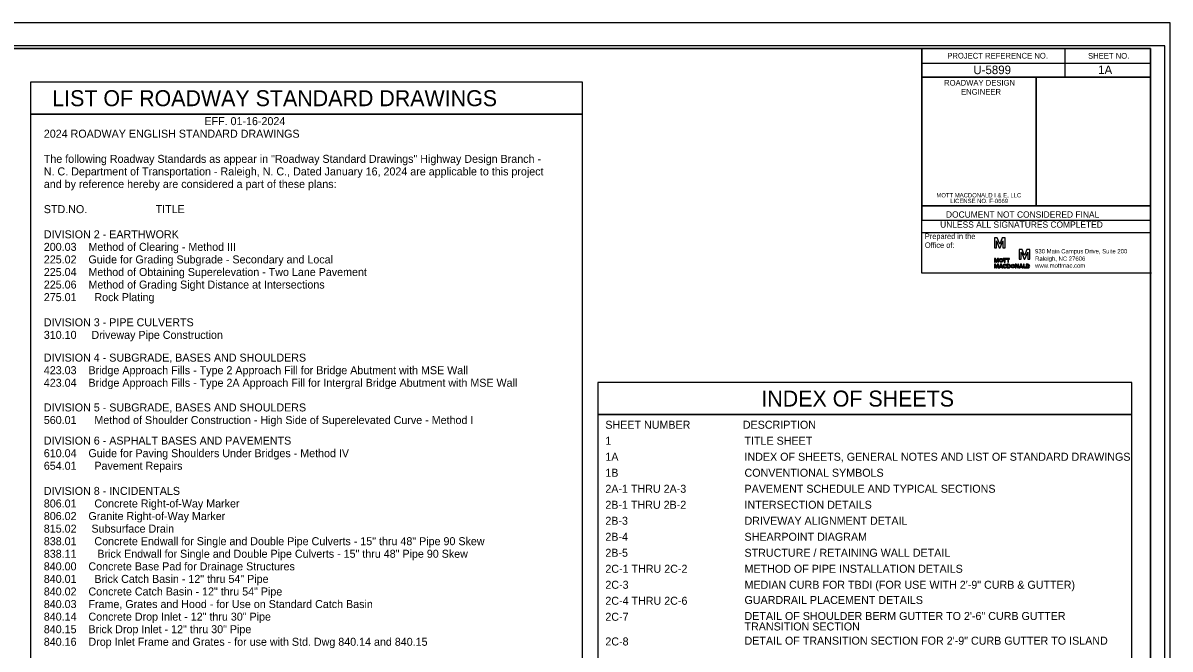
# Model space of a CAD drawing. Extents: x 93723152 to 93807327, y 70087853 to 70142603.
# Drawn here: x 93757166 to 93807327, y 70115212 to 70142603 of the extents above; entities that cross this region are included whole.
import ezdxf

# ---------------------------------------------------------------- set-up
doc = ezdxf.new("R2010")
doc.units = 0
for name, color, linetype in [('Default', 7, 'Continuous'), ('Old_Level_1', 7, 'Continuous'), ('Old_Level_2', 7, 'Continuous'), ('Old_Level_40', 7, 'Continuous'), ('Old_Level_42', 7, 'Continuous'), ('Old_Level_45', 7, 'Continuous'), ('Sheet Cutting Line CELL', 7, 'Continuous'), ('Sheet Data Field CELL', 7, 'Continuous'), ('Sheet Plan CELL', 7, 'Continuous'), ('Sheet Plot Border Inside CELL', 7, 'Continuous'), ('Sheet Plot Border Outside CELL', 7, 'Continuous'), ('Sheet Sticker Exception Certification CELL', 7, 'Continuous')]:
    doc.layers.add(name, color=color, linetype=linetype)

msp = doc.modelspace()

# ---------------------------------------------------------------- linework, layer by layer
at = {"layer": 'Old_Level_1'}
for points in [[(93757503, 70098101), (93781631, 70098101), (93781631, 70138611), (93757503, 70138611)], [(93782306, 70100674), (93805663, 70100674), (93805663, 70125470), (93782306, 70125470)]]:
    msp.add_lwpolyline(points, close=True, dxfattribs=at)
at = {"layer": 'Old_Level_2'}
for p, q in [((93799774, 70133195), (93799648, 70133195)), ((93799648, 70133195), (93799648, 70132768)), ((93799738, 70132768), (93799738, 70133075)), ((93799738, 70133075), (93799739, 70133075)), ((93799739, 70133075), (93799859, 70132768)), ((93799877, 70132931), (93799774, 70133195)), ((93799877, 70132927), (93799877, 70132931)), ((93799880, 70132927), (93799877, 70132927)), ((93799983, 70133195), (93799880, 70132931)), ((93799880, 70132931), (93799880, 70132927)), ((93799898, 70132768), (93800018, 70133076)), ((93800110, 70133195), (93799983, 70133195)), ((93800018, 70133076), (93800020, 70133076)), ((93800020, 70133076), (93800020, 70132768)), ((93800110, 70132768), (93800110, 70133195)), ((93799648, 70132768), (93799738, 70132768)), ((93799696, 70132301), (93799648, 70132301)), ((93799648, 70132301), (93799648, 70132138)), ((93799736, 70132199), (93799696, 70132301)), ((93799777, 70132301), (93799736, 70132199)), ((93799825, 70132301), (93799777, 70132301)), ((93799825, 70132138), (93799825, 70132301)), ((93799859, 70132768), (93799898, 70132768)), ((93800020, 70132768), (93800110, 70132768)), ((93800859, 70132698), (93800733, 70132698)), ((93800733, 70132698), (93800733, 70132271)), ((93800823, 70132271), (93800823, 70132578)), ((93800823, 70132578), (93800824, 70132578)), ((93800824, 70132578), (93800944, 70132271)), ((93800962, 70132434), (93800859, 70132698)), ((93800962, 70132430), (93800962, 70132434)), ((93800965, 70132430), (93800962, 70132430)), ((93801068, 70132698), (93800965, 70132434)), ((93800965, 70132434), (93800965, 70132430)), ((93800983, 70132271), (93801103, 70132579)), ((93801195, 70132698), (93801068, 70132698)), ((93801103, 70132579), (93801105, 70132579)), ((93801105, 70132579), (93801105, 70132271)), ((93801195, 70132271), (93801195, 70132698)), ((93799648, 70132138), (93799682, 70132138)), ((93799696, 70132048), (93799648, 70132048)), ((93799648, 70132048), (93799648, 70131885)), ((93799648, 70131885), (93799682, 70131885)), ((93799682, 70132138), (93799682, 70132255)), ((93799682, 70132255), (93799683, 70132255)), ((93799682, 70132255), (93799683, 70132255)), ((93799682, 70131885), (93799682, 70132002)), ((93799682, 70132002), (93799683, 70132002)), ((93799683, 70132255), (93799729, 70132138)), ((93799683, 70132002), (93799729, 70131885)), ((93799736, 70131946), (93799696, 70132048)), ((93799729, 70132138), (93799744, 70132138)), ((93799729, 70131885), (93799744, 70131885)), ((93799777, 70132048), (93799736, 70131946)), ((93799744, 70132138), (93799790, 70132255)), ((93799744, 70131885), (93799790, 70132002)), ((93799825, 70132048), (93799777, 70132048)), ((93799790, 70132255), (93799791, 70132255)), ((93799790, 70132255), (93799791, 70132255)), ((93799790, 70132255), (93799791, 70132255)), ((93799790, 70132002), (93799791, 70132002)), ((93799791, 70132255), (93799791, 70132138)), ((93799791, 70132138), (93799825, 70132138)), ((93799791, 70132002), (93799791, 70131885)), ((93799791, 70131885), (93799825, 70131885)), ((93799825, 70131885), (93799825, 70132048)), ((93800168, 70131918), (93800140, 70131932)), ((93800168, 70131918), (93800140, 70131932)), ((93800143, 70131995), (93800172, 70132008)), ((93800143, 70131995), (93800172, 70132008)), ((93800269, 70132048), (93800194, 70132048)), ((93800194, 70132048), (93800194, 70131963)), ((93800194, 70131963), (93800194, 70131885)), ((93800194, 70131885), (93800269, 70131885)), ((93800228, 70131916), (93800228, 70132018)), ((93800228, 70132018), (93800269, 70132018)), ((93800269, 70131916), (93800228, 70131916)), ((93800733, 70132271), (93800823, 70132271)), ((93800944, 70132271), (93800983, 70132271)), ((93801039, 70132048), (93801039, 70132048)), ((93801113, 70132048), (93801039, 70132048)), ((93801039, 70132048), (93801039, 70131963)), ((93801039, 70131963), (93801039, 70131885)), ((93801039, 70131885), (93801113, 70131885)), ((93801073, 70131916), (93801073, 70132018)), ((93801073, 70132018), (93801113, 70132018)), ((93801113, 70131916), (93801073, 70131916)), ((93801105, 70132271), (93801195, 70132271)), ((93801113, 70132017), (93801113, 70132017))]:
    msp.add_line(p, q, dxfattribs=at)
for points in [[(93800030, 70132271), (93800077, 70132271), (93800077, 70132138), (93800112, 70132138), (93800112, 70132271), (93800159, 70132271), (93800159, 70132301), (93800030, 70132301), (93800030, 70132271)], [(93800180, 70132271), (93800227, 70132271), (93800227, 70132138), (93800262, 70132138), (93800262, 70132271), (93800309, 70132271), (93800309, 70132301), (93800180, 70132301), (93800180, 70132271)], [(93799845, 70131885), (93799884, 70131885), (93799894, 70131912), (93799965, 70131912), (93799975, 70131885), (93800013, 70131885), (93799950, 70132048), (93799907, 70132048), (93799845, 70131885)], [(93799903, 70131942), (93799930, 70132013), (93799956, 70131942), (93799903, 70131942)], [(93800594, 70131990), (93800595, 70131990), (93800673, 70131885), (93800706, 70131885), (93800706, 70132048), (93800672, 70132048), (93800672, 70131945), (93800595, 70132048), (93800561, 70132048), (93800561, 70131885), (93800594, 70131885), (93800594, 70131990)], [(93800727, 70131885), (93800766, 70131885), (93800776, 70131912), (93800847, 70131912), (93800857, 70131885), (93800895, 70131885), (93800833, 70132048), (93800789, 70132048), (93800727, 70131885)], [(93800786, 70131942), (93800812, 70132013), (93800838, 70131942), (93800786, 70131942)], [(93801019, 70131885), (93801019, 70131913), (93800949, 70131913), (93800949, 70132048), (93800915, 70132048), (93800915, 70131885), (93801019, 70131885)]]:
    msp.add_lwpolyline(points, dxfattribs=at)
msp.add_arc((93801113, 70131966), 81.6, 270, 90, dxfattribs=at)
for centre, major_axis, ratio in [((93799936, 70132219), (0, 81.6), 0.993118), ((93799936, 70132219), (0.1, 53.1), 0.916103), ((93800452, 70131966), (0, 81.6), 0.993118), ((93800452, 70131966), (0.1, 53.1), 0.916103)]:
    msp.add_ellipse(centre, major_axis=major_axis, ratio=ratio, dxfattribs=at)
for centre, major_axis, ratio, start_param, end_param in [((93800102, 70131966), (0, 81.6), 0.993118, 5.246647, 10.366427), ((93800102, 70131966), (0.1, 53.1), 0.916103, 5.276876, 10.296021), ((93800269, 70131966), (0, -81.5), 0.930276, 0, 3.141593), ((93800269, 70131967), (0, -50.9), 0.900832, 0, 3.141593), ((93801113, 70131967), (0, -50.9), 0.900832, 0, 3.141593)]:
    msp.add_ellipse(centre, major_axis=major_axis, ratio=ratio, start_param=start_param, end_param=end_param, dxfattribs=at)
at = {"layer": 'Old_Level_40'}
for points in [[(93757503, 70138611), (93781631, 70138611), (93781631, 70140011), (93757503, 70140011)], [(93782305, 70125470), (93805663, 70125470), (93805663, 70126870), (93782305, 70126870)]]:
    msp.add_lwpolyline(points, close=True, dxfattribs=at)
at = {"layer": 'Old_Level_42'}
msp.add_lwpolyline([(93806520, 70131654), (93796477, 70131654), (93796477, 70133426)], dxfattribs=at)
at = {"layer": 'Sheet Cutting Line CELL'}
msp.add_line((93807327, 70142603), (93723152, 70142603), dxfattribs=at)
at = {"layer": 'Sheet Plan CELL'}
for p, q in [((93802727, 70141475), (93802727, 70140225)), ((93796475, 70140850), (93806477, 70140850)), ((93796475, 70140225), (93806477, 70140225)), ((93796475, 70140225), (93806477, 70140225)), ((93801477, 70140225), (93801477, 70134603))]:
    msp.add_line(p, q, dxfattribs=at)
for points in [[(93731477, 70088977), (93731476, 70141476), (93796475, 70141478), (93796476, 70133975), (93806477, 70133974), (93806477, 70088977)], [(93806477, 70141478), (93731477, 70141478), (93731477, 70088978), (93806477, 70088978)], [(93796475, 70141478), (93806477, 70141478), (93806477, 70140225), (93796475, 70140225)], [(93796477, 70140225), (93801477, 70140225), (93801477, 70134600), (93796477, 70134600)], [(93801477, 70140225), (93806477, 70140225), (93806477, 70134600), (93801477, 70134600)]]:
    msp.add_lwpolyline(points, close=True, dxfattribs=at)
at = {"layer": 'Sheet Plot Border Inside CELL'}
msp.add_lwpolyline([(93723802, 70088853), (93807102, 70088853), (93807102, 70141603), (93723802, 70141603)], close=True, dxfattribs=at)
at = {"layer": 'Sheet Plot Border Outside CELL'}
msp.add_lwpolyline([(93723152, 70087853), (93807327, 70087853), (93807327, 70142603), (93723152, 70142603)], close=True, dxfattribs=at)
at = {"layer": 'Sheet Sticker Exception Certification CELL'}
for p, q in [((93796476, 70133426), (93796476, 70134601)), ((93796476, 70134601), (93806477, 70134601)), ((93806477, 70134600), (93806477, 70133425)), ((93806477, 70133426), (93796476, 70133426))]:
    msp.add_line(p, q, dxfattribs=at)

# ---------------------------------------------------------------- texts
at = {"layer": 'Default'}
for s, p in [('838.01      Concrete Endwall for Single and Double Pipe Culverts - 15" thru 48" Pipe 90 Skew', (93758079, 70119756)), ('838.11       Brick Endwall for Single and Double Pipe Culverts - 15" thru 48" Pipe 90 Skew', (93758079, 70119206)), ('840.01      Brick Catch Basin - 12" thru 54" Pipe', (93758079, 70118106)), ('840.02    Concrete Catch Basin - 12" thru 54" Pipe', (93758079, 70117556))]:
    msp.add_text(s, height=350, dxfattribs=at).set_placement(p)
at = {"layer": 'Old_Level_1'}
for s, p in [('                                                      EFF. 01-16-2024', (93758079, 70138132)), ('2024 ROADWAY ENGLISH STANDARD DRAWINGS', (93758079, 70137582)), ('The following Roadway Standards as appear in "Roadway Standard Drawings" Highway Design Branch -', (93758079, 70136482)), ('N. C. Department of Transportation - Raleigh, N. C., Dated January 16, 2024 are applicable to this project', (93758079, 70135932)), ('and by reference hereby are considered a part of these plans:', (93758079, 70135382)), ('STD.NO.                       TITLE', (93758079, 70134282)), ('DIVISION 2 - EARTHWORK', (93758079, 70133182)), ('200.03    Method of Clearing - Method III', (93758079, 70132632)), ('225.02    Guide for Grading Subgrade - Secondary and Local', (93758079, 70132082)), ('225.04    Method of Obtaining Superelevation - Two Lane Pavement', (93758079, 70131532)), ('225.06    Method of Grading Sight Distance at Intersections', (93758079, 70130982)), ('275.01      Rock Plating', (93758079, 70130432)), ('DIVISION 3 - PIPE CULVERTS', (93758079, 70129332)), ('310.10     Driveway Pipe Construction ', (93758079, 70128782)), ('DIVISION 4 - SUBGRADE, BASES AND SHOULDERS', (93758079, 70127787)), ('423.03    Bridge Approach Fills - Type 2 Approach Fill for Bridge Abutment with MSE Wall', (93758079, 70127237)), ('423.04    Bridge Approach Fills - Type 2A Approach Fill for Intergral Bridge Abutment with MSE Wall', (93758079, 70126687)), ('DIVISION 5 - SUBGRADE, BASES AND SHOULDERS', (93758079, 70125607)), ('560.01      Method of Shoulder Construction - High Side of Superelevated Curve - Method I', (93758079, 70125057)), ('SHEET NUMBER', (93782633, 70124850)), ('DESCRIPTION', (93788646, 70124850)), ('DIVISION 6 - ASPHALT BASES AND PAVEMENTS', (93758079, 70124156)), ('1 ', (93782634, 70124150)), ('TITLE SHEET', (93788718, 70124150)), ('610.04    Guide for Paving Shoulders Under Bridges - Method IV', (93758079, 70123606)), ('1A ', (93782634, 70123450)), ('INDEX OF SHEETS, GENERAL NOTES AND LIST OF STANDARD DRAWINGS', (93788718, 70123450)), ('654.01      Pavement Repairs', (93758079, 70123056)), ('1B  ', (93782634, 70122750)), ('CONVENTIONAL SYMBOLS ', (93788719, 70122750)), ('DIVISION 8 - INCIDENTALS', (93758079, 70121956)), ('2A-1 THRU 2A-3', (93782634, 70122050)), ('PAVEMENT SCHEDULE AND TYPICAL SECTIONS', (93788719, 70122050)), ('806.01      Concrete Right-of-Way Marker', (93758079, 70121406)), ('2B-1 THRU 2B-2', (93782634, 70121350)), ('INTERSECTION DETAILS', (93788719, 70121350)), ('806.02    Granite Right-of-Way Marker', (93758079, 70120856)), ('2B-3', (93782634, 70120650)), ('DRIVEWAY ALIGNMENT DETAIL', (93788719, 70120650)), ('815.02     Subsurface Drain', (93758079, 70120306)), ('2B-4', (93782634, 70119950)), ('SHEARPOINT DIAGRAM', (93788719, 70119950)), ('2B-5', (93782634, 70119250)), ('STRUCTURE / RETAINING WALL DETAIL', (93788719, 70119250)), ('840.00    Concrete Base Pad for Drainage Structures', (93758079, 70118656)), ('2C-1 THRU 2C-2   ', (93782634, 70118550)), ('METHOD OF PIPE INSTALLATION DETAILS', (93788719, 70118550)), ('2C-3  ', (93782634, 70117850)), ('MEDIAN CURB FOR TBDI (FOR USE WITH 2\'-9" CURB & GUTTER)', (93788719, 70117850)), ('840.03    Frame, Grates and Hood - for Use on Standard Catch Basin', (93758079, 70117006)), ('2C-4 THRU 2C-6', (93782634, 70117150)), ('GUARDRAIL PLACEMENT DETAILS', (93788719, 70117184)), ('840.14    Concrete Drop Inlet - 12" thru 30" Pipe', (93758079, 70116456)), ('2C-7', (93782634, 70116450)), ('DETAIL OF SHOULDER BERM GUTTER TO 2\'-6" CURB GUTTER', (93788719, 70116484)), ('840.15    Brick Drop Inlet - 12" thru 30" Pipe', (93758079, 70115906)), ('TRANSITION SECTION', (93788719, 70116025)), ('DETAIL OF TRANSITION SECTION FOR 2\'-9" CURB GUTTER TO ISLAND', (93788719, 70115404)), ('840.16    Drop Inlet Frame and Grates - for use with Std. Dwg 840.14 and 840.15', (93758079, 70115356)), ('2C-8', (93782634, 70115370))]:
    msp.add_text(s, height=350, dxfattribs=at).set_placement(p)
at = {"layer": 'Old_Level_2'}
for s, height, p in [('Prepared in the ', 241.9, (93796605, 70133150)), ('Office of:', 241.9, (93796605, 70132761)), ('930 Main Campus Drive, Suite 200', 188.26, (93801426, 70132521)), ('Raleigh, NC 27606', 188.26, (93801426, 70132197)), ('www.mottmac.com', 188.26, (93801426, 70131892))]:
    msp.add_text(s, height=height, rotation=360, dxfattribs=at).set_placement(p)
at = {"layer": 'Old_Level_40'}
for s, p in [('LIST OF ROADWAY STANDARD DRAWINGS', (93758448, 70138961)), ('INDEX OF SHEETS', (93789455, 70125820))]:
    msp.add_text(s, height=700, dxfattribs=at).set_placement(p)
at = {"layer": 'Old_Level_45'}
for s, p in [('MOTT MACDONALD I & E, LLC', (93797108, 70134972)), (' LICENSE NO. F-0669', (93797640, 70134722))]:
    msp.add_text(s, height=187.5, dxfattribs=at).set_placement(p)
at = {"layer": 'Sheet Data Field CELL'}
for s, p in [('U-5899', (93798726, 70140363)), ('1A ', (93804183, 70140365))]:
    msp.add_text(s, height=375, dxfattribs=at).set_placement(p)
at = {"layer": 'Sheet Plan CELL'}
for s, p in [('PROJECT REFERENCE NO.', (93797585, 70141043)), ('SHEET NO.', (93803742, 70141038)), ('ROADWAY DESIGN', (93797447, 70139860)), ('ENGINEER', (93798190, 70139463))]:
    msp.add_text(s, height=250, dxfattribs=at).set_placement(p)
at = {"layer": 'Sheet Sticker Exception Certification CELL'}
for s, p in [('DOCUMENT NOT CONSIDERED FINAL', (93797529, 70134084)), ('UNLESS ALL SIGNATURES COMPLETED', (93797275, 70133644))]:
    msp.add_text(s, height=275, dxfattribs=at).set_placement(p)

doc.saveas('drawing.dxf')
